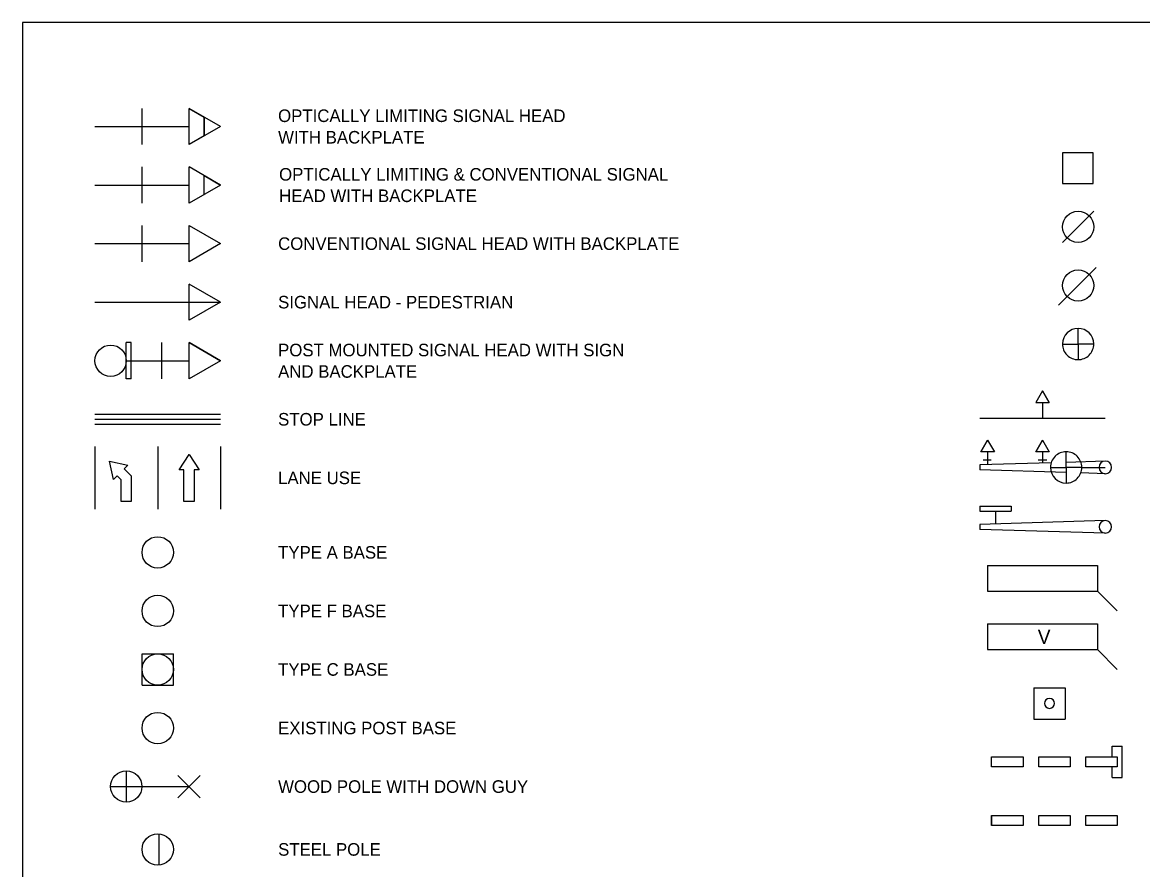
# Model space of a CAD drawing. Extents: x -439.1 to -407.9, y -458.1 to -437.7.
# Drawn here: x -439.11 to -425.73, y -447.8 to -437.68 of the extents above; entities that cross this region are included whole.
import ezdxf

# ---------------------------------------------------------------- set-up
doc = ezdxf.new("R2010")
doc.units = 0
for name, color, linetype in [('Draft_Named_Boundary', 7, 'Continuous'), ('Level 4', 7, 'Continuous'), ('Lighting_Signals-Equipment', 7, 'Continuous')]:
    doc.layers.add(name, color=color, linetype=linetype)

msp = doc.modelspace()

# ---------------------------------------------------------------- linework, layer by layer
at = {"layer": 'Draft_Named_Boundary'}
msp.add_lwpolyline([(-439.109, -458.051), (-407.859, -458.051), (-407.859, -437.676), (-439.109, -437.676)], close=True, dxfattribs=at)
at = {"layer": 'Level 4'}
for p, q in [((-437.68, -439.136), (-437.68, -438.703)), ((-437.119, -439.136), (-437.119, -438.703)), ((-436.744, -438.919), (-437.119, -438.703)), ((-436.938, -439.032), (-436.938, -438.807)), ((-438.243, -438.919), (-437.119, -438.919)), ((-436.744, -438.919), (-437.119, -439.136)), ((-437.68, -439.835), (-437.68, -439.403)), ((-436.744, -439.619), (-437.119, -439.403)), ((-437.119, -439.835), (-437.119, -439.403)), ((-436.938, -439.732), (-436.938, -439.506)), ((-438.243, -439.619), (-437.119, -439.619)), ((-436.744, -439.619), (-437.119, -439.835)), ((-426.313, -439.932), (-426.687, -440.307)), ((-437.68, -440.535), (-437.68, -440.102)), ((-437.119, -440.102), (-436.744, -440.319)), ((-437.119, -440.535), (-437.119, -440.102)), ((-438.243, -440.319), (-437.119, -440.319)), ((-436.744, -440.319), (-437.119, -440.535)), ((-426.284, -440.602), (-426.735, -441.053)), ((-436.744, -441.018), (-437.119, -440.802)), ((-437.119, -441.234), (-437.119, -440.802)), ((-438.243, -441.018), (-436.744, -441.018)), ((-436.744, -441.018), (-437.119, -441.234)), ((-426.5, -441.518), (-426.5, -441.331)), ((-437.868, -441.934), (-437.868, -441.501)), ((-437.808, -441.501), (-437.868, -441.501)), ((-437.808, -441.934), (-437.808, -441.501)), ((-437.444, -441.934), (-437.444, -441.501)), ((-436.744, -441.718), (-437.119, -441.501)), ((-437.119, -441.934), (-437.119, -441.501)), ((-426.688, -441.518), (-426.5, -441.518)), ((-426.313, -441.518), (-426.5, -441.518)), ((-426.5, -441.518), (-426.5, -441.706)), ((-426.313, -441.518), (-426.313, -441.518)), ((-437.868, -441.718), (-437.119, -441.718)), ((-436.744, -441.718), (-437.119, -441.934)), ((-437.808, -441.934), (-437.868, -441.934)), ((-426.925, -442.078), (-427.006, -442.218)), ((-426.925, -442.078), (-426.844, -442.218)), ((-427.006, -442.218), (-426.844, -442.218)), ((-426.925, -442.218), (-426.925, -442.405)), ((-438.243, -442.357), (-436.744, -442.357)), ((-438.243, -442.417), (-436.744, -442.417)), ((-427.674, -442.405), (-426.175, -442.405)), ((-438.243, -442.477), (-436.744, -442.477)), ((-427.581, -442.665), (-427.662, -442.805)), ((-427.581, -442.665), (-427.499, -442.805)), ((-426.924, -442.665), (-427.006, -442.805)), ((-426.924, -442.665), (-426.844, -442.805)), ((-438.243, -442.742), (-438.243, -443.492)), ((-437.493, -442.742), (-437.493, -443.492)), ((-437.238, -443.023), (-437.119, -442.836)), ((-437.128, -442.85), (-437.116, -442.839)), ((-437.119, -442.836), (-436.998, -443.023)), ((-436.744, -442.742), (-436.744, -443.492)), ((-427.581, -442.805), (-427.581, -442.959)), ((-426.924, -442.805), (-426.924, -442.94)), ((-426.643, -442.992), (-426.643, -442.805)), ((-438.019, -443.135), (-438.067, -442.918)), ((-438.067, -442.918), (-437.849, -442.965)), ((-437.849, -442.965), (-437.892, -443.008)), ((-426.823, -442.937), (-427.674, -442.962)), ((-427.674, -442.962), (-427.674, -443.023)), ((-427.633, -442.902), (-427.538, -442.902)), ((-426.976, -442.902), (-426.872, -442.902)), ((-426.175, -442.917), (-426.643, -442.932)), ((-437.977, -443.093), (-438.019, -443.135)), ((-437.928, -443.142), (-437.977, -443.093)), ((-437.892, -443.008), (-437.808, -443.092)), ((-437.808, -443.092), (-437.808, -443.398)), ((-437.179, -443.023), (-437.238, -443.023)), ((-437.179, -443.398), (-437.179, -443.023)), ((-436.998, -443.023), (-437.059, -443.023)), ((-437.059, -443.023), (-437.059, -443.398)), ((-426.643, -443.053), (-427.674, -443.023)), ((-426.831, -442.992), (-426.643, -442.992)), ((-426.456, -442.992), (-426.643, -442.992)), ((-426.643, -442.992), (-426.643, -443.18)), ((-426.175, -443.067), (-426.468, -443.059)), ((-426.456, -442.992), (-426.175, -442.992)), ((-437.928, -443.398), (-437.928, -443.142)), ((-437.808, -443.398), (-437.928, -443.398)), ((-437.059, -443.398), (-437.179, -443.398)), ((-427.674, -443.455), (-427.3, -443.455)), ((-427.674, -443.455), (-427.674, -443.515)), ((-427.674, -443.515), (-427.3, -443.515)), ((-427.487, -443.515), (-427.487, -443.667)), ((-427.3, -443.455), (-427.3, -443.515)), ((-426.175, -443.627), (-427.674, -443.673)), ((-427.674, -443.673), (-427.674, -443.733)), ((-426.175, -443.777), (-427.674, -443.733)), ((-427.581, -444.163), (-427.581, -444.47)), ((-427.581, -444.163), (-426.269, -444.163)), ((-426.269, -444.163), (-426.269, -444.47)), ((-427.581, -444.47), (-426.269, -444.47)), ((-426.269, -444.47), (-426.033, -444.705)), ((-427.581, -444.862), (-427.581, -445.169)), ((-427.581, -444.862), (-426.269, -444.862)), ((-426.269, -444.862), (-426.269, -445.169)), ((-437.68, -445.218), (-437.306, -445.218)), ((-437.68, -445.594), (-437.68, -445.218)), ((-437.306, -445.594), (-437.306, -445.218)), ((-427.581, -445.169), (-426.269, -445.169)), ((-426.269, -445.169), (-426.033, -445.405)), ((-437.68, -445.594), (-437.306, -445.594)), ((-427.028, -445.624), (-427.028, -445.998)), ((-427.028, -445.624), (-426.654, -445.624)), ((-426.654, -445.624), (-426.654, -445.998)), ((-427.028, -445.998), (-426.654, -445.998)), ((-426.093, -446.324), (-425.974, -446.324)), ((-426.093, -446.451), (-426.093, -446.324)), ((-425.974, -446.698), (-425.974, -446.324)), ((-427.533, -446.571), (-427.533, -446.451)), ((-427.533, -446.451), (-427.157, -446.451)), ((-427.157, -446.451), (-427.157, -446.571)), ((-426.97, -446.571), (-426.97, -446.451)), ((-426.97, -446.451), (-426.595, -446.451)), ((-426.595, -446.451), (-426.595, -446.571)), ((-426.408, -446.571), (-426.408, -446.451)), ((-426.408, -446.451), (-426.033, -446.451)), ((-426.033, -446.451), (-426.033, -446.571)), ((-427.157, -446.571), (-427.533, -446.571)), ((-426.595, -446.571), (-426.97, -446.571)), ((-426.033, -446.571), (-426.408, -446.571)), ((-426.093, -446.698), (-426.093, -446.571)), ((-437.868, -446.618), (-437.868, -446.993)), ((-436.986, -446.673), (-437.251, -446.938)), ((-437.251, -446.673), (-436.986, -446.938)), ((-426.093, -446.698), (-425.974, -446.698)), ((-438.055, -446.805), (-437.119, -446.805)), ((-427.533, -447.15), (-427.533, -447.271)), ((-427.533, -447.271), (-427.533, -447.15)), ((-427.533, -447.271), (-427.533, -447.15)), ((-427.533, -447.15), (-427.157, -447.15)), ((-427.157, -447.271), (-427.533, -447.271)), ((-427.157, -447.15), (-427.157, -447.271)), ((-426.97, -447.271), (-426.97, -447.15)), ((-426.97, -447.15), (-426.595, -447.15)), ((-426.595, -447.271), (-426.97, -447.271)), ((-426.595, -447.15), (-426.595, -447.271)), ((-426.408, -447.271), (-426.408, -447.15)), ((-426.408, -447.15), (-426.033, -447.15)), ((-426.033, -447.271), (-426.408, -447.271)), ((-426.033, -447.15), (-426.033, -447.271)), ((-437.481, -447.37), (-437.481, -447.743))]:
    msp.add_line(p, q, dxfattribs=at)
for points in [[(-437.119, -438.703), (-436.938, -438.807), (-436.938, -439.032), (-437.119, -439.136)], [(-436.938, -439.506), (-436.744, -439.619), (-436.938, -439.732)], [(-436.744, -441.018), (-437.119, -441.234), (-437.119, -441.018)], [(-437.119, -441.501), (-436.744, -441.718), (-437.119, -441.934)], [(-426.925, -442.078), (-427.006, -442.218), (-426.844, -442.218)], [(-427.662, -442.805), (-427.581, -442.665), (-427.499, -442.805)], [(-427.006, -442.805), (-426.924, -442.665), (-426.844, -442.805)]]:
    msp.add_lwpolyline(points, close=True, dxfattribs=at)
for centre in [(-426.5, -440.119), (-426.5, -440.819), (-438.055, -441.718), (-437.493, -444.007), (-437.493, -444.707), (-437.493, -445.406), (-437.493, -446.106), (-437.868, -446.805), (-437.493, -447.556)]:
    msp.add_circle(centre, 0.187, dxfattribs=at)
for centre, radius, start, end in [((-426.5, -441.518), 0.187, 89.9559, 179.9354), ((-426.5, -441.518), 0.187, 0.0646, 89.9559), ((-426.5, -441.518), 0.187, 179.9366, 270.0444), ((-426.5, -441.518), 0.187, 270.0444, 0.0635), ((-426.643, -442.992), 0.187, 89.9177, 180.0052), ((-426.643, -442.992), 0.187, 359.9996, 90.0025), ((-426.175, -442.992), 0.0751, 0, 180), ((-426.643, -442.992), 0.187, 180.0004, 269.9975), ((-426.643, -442.992), 0.187, 269.9975, 359.9996), ((-426.175, -442.992), 0.0751, 180, 0), ((-426.175, -443.702), 0.0751, 0, 180), ((-426.175, -443.702), 0.0751, 180, 0), ((-426.841, -445.811), 0.06, 0, 180), ((-426.841, -445.811), 0.06, 180, 0)]:
    msp.add_arc(centre, radius, start, end, dxfattribs=at)
at = {"layer": 'Lighting_Signals-Equipment'}
msp.add_lwpolyline([(-426.688, -439.602), (-426.32, -439.602), (-426.32, -439.234), (-426.688, -439.234)], close=True, dxfattribs=at)

# ---------------------------------------------------------------- texts
at = {"layer": 'Level 4'}
for s, height, p in [('OPTICALLY LIMITING SIGNAL HEAD', 0.15, (-436.055, -438.866)), ('WITH BACKPLATE', 0.15, (-436.055, -439.123)), ('OPTICALLY LIMITING & CONVENTIONAL SIGNAL', 0.15, (-436.043, -439.566)), ('HEAD WITH BACKPLATE', 0.15, (-436.043, -439.822)), ('CONVENTIONAL SIGNAL HEAD WITH BACKPLATE', 0.15, (-436.055, -440.394)), ('SIGNAL HEAD - PEDESTRIAN', 0.15, (-436.055, -441.093)), ('POST MOUNTED SIGNAL HEAD WITH SIGN', 0.15, (-436.055, -441.665)), ('AND BACKPLATE', 0.15, (-436.055, -441.921)), ('STOP LINE', 0.15, (-436.055, -442.492)), ('LANE USE', 0.15, (-436.055, -443.192)), ('TYPE A BASE', 0.15, (-436.055, -444.082)), ('TYPE F BASE', 0.15, (-436.055, -444.782)), ('V', 0.171, (-426.982, -445.101)), ('TYPE C BASE', 0.15, (-436.055, -445.481)), ('EXISTING POST BASE', 0.15, (-436.055, -446.181)), ('WOOD POLE WITH DOWN GUY', 0.15, (-436.055, -446.88)), ('STEEL POLE', 0.15, (-436.055, -447.631))]:
    msp.add_text(s, height=height, dxfattribs=at).set_placement(p)

doc.saveas('drawing.dxf')
